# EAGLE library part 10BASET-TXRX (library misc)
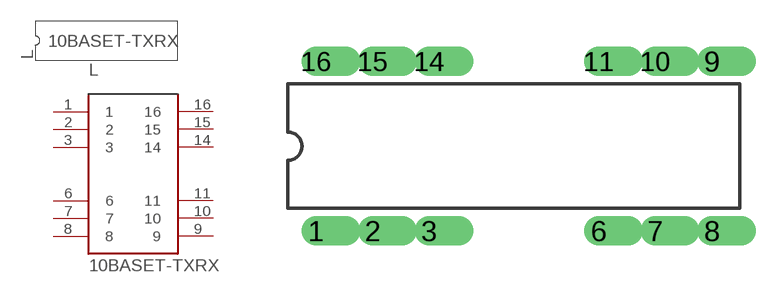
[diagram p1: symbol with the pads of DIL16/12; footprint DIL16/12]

Designator prefix L

## 10BASET-TXRX  [DIL16/12]
1  1  pas
2  2  pas
3  3  pas
6  6  pas
7  7  pas
8  8  pas
9  9  pas
10  10  pas
11  11  pas
14  14  pas
15  15  pas
16  16  pas

## Footprint DIL16/12 (pad centres in mm)
drill 0.813 offset: 1 -8.89,-3.81; 2 -6.35,-3.81; 3 -3.81,-3.81; 6 3.81,-3.81; 7 6.35,-3.81; 8 8.89,-3.81; 9 8.89,3.81; 10 6.35,3.81; 11 3.81,3.81; 14 -3.81,3.81; 15 -6.35,3.81; 16 -8.89,3.81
